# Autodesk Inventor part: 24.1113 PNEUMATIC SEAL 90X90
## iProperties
Created: 2007-06
Part Number: 24.1113 PNEUMATIC SEAL 90X90
Document SubType Name: Modeling
Designer: Andy Moles
Density: 1 g/cm^3
Mass: 11.0239 g
Surface Area: 155.196 cm^2
Volume: 11.0239 cm^3
Author: Andy Moles
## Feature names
1. Extrusion1
2. Fillet1
